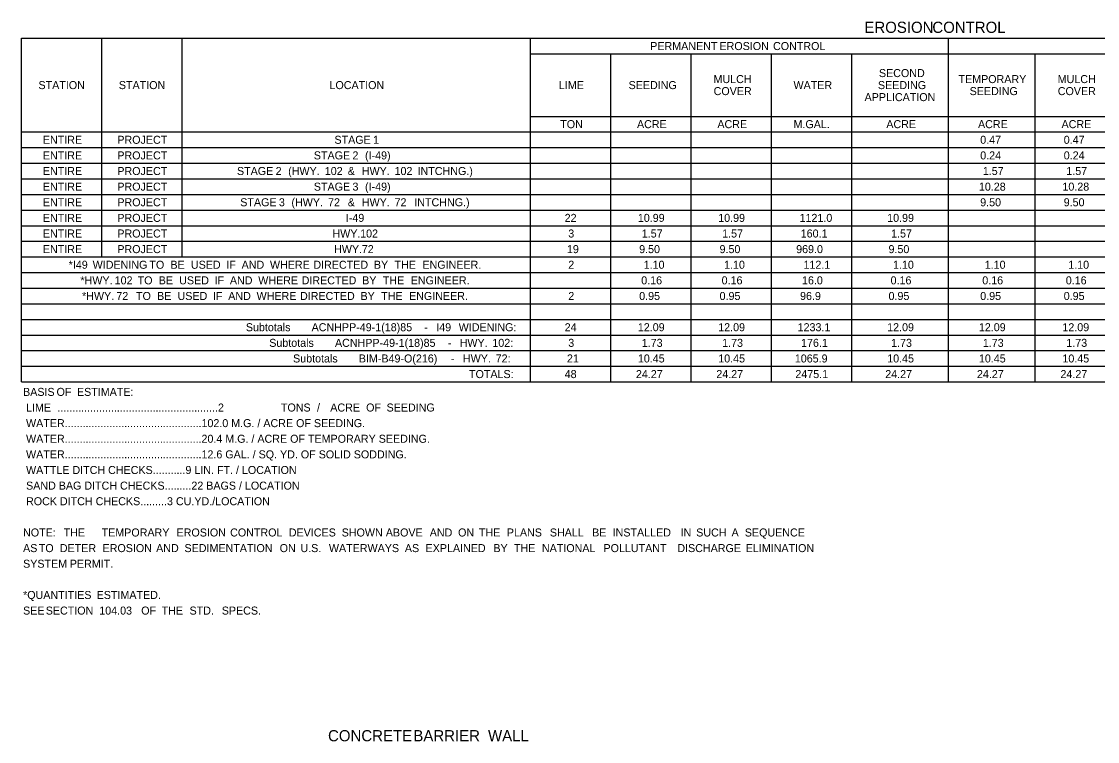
# Model space of a CAD drawing. Extents: x 1226589 to 1228130, y 151309 to 152305.
# Drawn here: x 1226589 to 1227261, y 151844 to 152293 of the extents above; entities that cross this region are included whole.
import ezdxf

# ---------------------------------------------------------------- set-up
doc = ezdxf.new("R2010")
doc.units = 0
doc.layers.add('R_Dimension', color=7, linetype='Continuous')

msp = doc.modelspace()

# ---------------------------------------------------------------- linework, layer by layer
at = {"layer": 'R_Dimension'}
for p, q in [((1226588.59, 152283.05), (1227732.75, 152283.05)), ((1226588.59, 152068.55), (1226588.59, 152283.05)), ((1226638.8, 152146.55), (1226638.8, 152283.05)), ((1226689.01, 152146.55), (1226689.01, 152283.05)), ((1226906.44, 152068.55), (1226906.44, 152283.05)), ((1227167.74, 152068.55), (1227167.74, 152283.05)), ((1226906.44, 152273.3), (1227732.75, 152273.3)), ((1226956.65, 152068.55), (1226956.65, 152273.3)), ((1227006.86, 152068.55), (1227006.86, 152273.3)), ((1227057.07, 152068.55), (1227057.07, 152273.3)), ((1227107.29, 152068.55), (1227107.29, 152273.3)), ((1227221.85, 152068.55), (1227221.85, 152273.3)), ((1226906.44, 152234.3), (1227732.75, 152234.3)), ((1226588.59, 152224.55), (1227732.75, 152224.55)), ((1226588.59, 152214.8), (1227732.75, 152214.8)), ((1226588.59, 152205.05), (1227732.75, 152205.05)), ((1226588.59, 152195.3), (1227732.75, 152195.3)), ((1226588.59, 152185.55), (1227732.75, 152185.55)), ((1226588.59, 152175.8), (1227732.75, 152175.8)), ((1226588.59, 152166.05), (1227732.75, 152166.05)), ((1226588.59, 152156.3), (1227732.75, 152156.3)), ((1226588.59, 152146.55), (1227732.75, 152146.55)), ((1226588.59, 152136.8), (1227732.75, 152136.8)), ((1226588.59, 152127.05), (1227732.75, 152127.05)), ((1226588.59, 152117.3), (1227732.75, 152117.3)), ((1226588.59, 152107.55), (1227732.75, 152107.55)), ((1226588.59, 152097.8), (1227732.75, 152097.8)), ((1226588.59, 152088.05), (1227732.75, 152088.05)), ((1226588.59, 152078.3), (1227732.75, 152078.3)), ((1226588.59, 152068.55), (1227732.75, 152068.55))]:
    msp.add_line(p, q, dxfattribs=at)

# ---------------------------------------------------------------- texts
for s, height, p in [('EROSION', 7, (1227115.09, 152286.37)), (' CONTROL', 7, (1227154.94, 152286.37)), ('PERMANENT', 5, (1226981.34, 152275.67)), (' EROSION', 5, (1227022.72, 152275.67)), (' CONTROL', 5, (1227056.18, 152275.67)), ('SECOND', 5, (1227124.19, 152258.8)), ('STATION', 5, (1226599.19, 152251.3)), ('STATION', 5, (1226649.4, 152251.3)), ('LOCATION', 5, (1226780.97, 152251.3)), ('LIME', 5, (1226924.26, 152251.3)), ('SEEDING', 5, (1226967.8, 152251.3)), ('MULCH', 5, (1227020.87, 152255.05)), ('WATER', 5, (1227070.82, 152251.3)), ('SEEDING', 5, (1227123.56, 152251.3)), ('TEMPORARY', 5, (1227173.89, 152255.05)), ('MULCH', 5, (1227235.85, 152255.05)), ('COVER', 5, (1227020.93, 152247.55)), ('APPLICATION', 5, (1227115.21, 152243.8)), ('SEEDING', 5, (1227180.84, 152247.55)), ('COVER', 5, (1227235.91, 152247.55)), ('TON', 5, (1226925.11, 152226.92)), ('ACRE', 5, (1226973.06, 152226.92)), ('ACRE', 5, (1227023.27, 152226.92)), ('M.GAL.', 5, (1227070.84, 152226.92)), ('ACRE', 5, (1227128.81, 152226.92)), ('ACRE', 5, (1227186.09, 152226.92)), ('ACRE', 5, (1227238.26, 152226.92)), ('ENTIRE', 5, (1226601.92, 152217.17)), ('PROJECT', 5, (1226648.45, 152217.17)), ('STAGE', 5, (1226784.08, 152217.17)), (' 1', 5, (1226806.37, 152217.17)), ('0.47', 5, (1227187.47, 152217.17)), ('0.47', 5, (1227239.63, 152217.17)), ('ENTIRE', 5, (1226601.92, 152207.42)), ('PROJECT', 5, (1226648.45, 152207.42)), ('STAGE', 5, (1226771.19, 152207.42)), (' 2', 5, (1226793.47, 152207.42)), (' (I-49)', 5, (1226801.31, 152207.42)), ('0.24', 5, (1227187.47, 152207.42)), ('0.24', 5, (1227239.63, 152207.42)), ('ENTIRE', 5, (1226601.92, 152197.67)), ('PROJECT', 5, (1226648.45, 152197.67)), ('STAGE', 5, (1226723.18, 152197.67)), (' 2', 5, (1226745.46, 152197.67)), (' (HWY.', 5, (1226753.3, 152197.67)), (' 102', 5, (1226776.17, 152197.67)), (' &', 5, (1226790.54, 152197.67)), (' HWY.', 5, (1226799.32, 152197.67)), (' 102', 5, (1226819.75, 152197.67)), (' INTCHNG.)', 5, (1226834.12, 152197.67)), ('1.57', 5, (1227189.08, 152197.67)), ('1.57', 5, (1227241.25, 152197.67)), ('ENTIRE', 5, (1226601.92, 152187.92)), ('PROJECT', 5, (1226648.45, 152187.92)), ('STAGE', 5, (1226771.19, 152187.92)), (' 3', 5, (1226793.47, 152187.92)), (' (I-49)', 5, (1226801.31, 152187.92)), ('10.28', 5, (1227186.64, 152187.92)), ('10.28', 5, (1227238.81, 152187.92)), ('ENTIRE', 5, (1226601.92, 152178.17)), ('PROJECT', 5, (1226648.45, 152178.17)), ('STAGE', 5, (1226725.22, 152178.17)), (' 3', 5, (1226747.51, 152178.17)), (' (HWY.', 5, (1226755.34, 152178.17)), (' 72', 5, (1226778.22, 152178.17)), (' &', 5, (1226790.54, 152178.17)), (' HWY.', 5, (1226799.32, 152178.17)), (' 72', 5, (1226819.75, 152178.17)), (' INTCHNG.)', 5, (1226832.08, 152178.17)), ('9.50', 5, (1227187.45, 152178.17)), ('9.50', 5, (1227239.61, 152178.17)), ('ENTIRE', 5, (1226601.92, 152168.42)), ('PROJECT', 5, (1226648.45, 152168.42)), ('I-49', 5, (1226791.17, 152168.42)), ('22', 5, (1226927.88, 152168.42)), ('10.99', 5, (1226973.59, 152168.42)), ('10.99', 5, (1227023.8, 152168.42)), ('1121.0', 5, (1227074.6, 152168.42)), ('10.99', 5, (1227129.34, 152168.42)), ('ENTIRE', 5, (1226601.92, 152158.67)), ('PROJECT', 5, (1226648.45, 152158.67)), ('HWY.', 5, (1226782.82, 152158.67)), (' 102', 5, (1226798.26, 152158.67)), ('3', 5, (1226930.13, 152158.67)), ('1.57', 5, (1226976.05, 152158.67)), ('1.57', 5, (1227026.26, 152158.67)), ('160.1', 5, (1227075.33, 152158.67)), ('1.57', 5, (1227131.8, 152158.67)), ('ENTIRE', 5, (1226601.92, 152148.92)), ('PROJECT', 5, (1226648.45, 152148.92)), ('HWY.', 5, (1226783.85, 152148.92)), (' 72', 5, (1226799.28, 152148.92)), ('19', 5, (1226929.28, 152148.92)), ('9.50', 5, (1226974.41, 152148.92)), ('9.50', 5, (1227024.63, 152148.92)), ('969.0', 5, (1227072.48, 152148.92)), ('9.50', 5, (1227130.17, 152148.92)), ('*I49', 5, (1226618.06, 152139.17)), (' WIDENING', 5, (1226631.17, 152139.17)), (' TO', 5, (1226666.61, 152139.17)), (' BE', 5, (1226679.76, 152139.17)), (' USED', 5, (1226692.55, 152139.17)), (' IF', 5, (1226714.68, 152139.17)), (' AND', 5, (1226724.21, 152139.17)), (' WHERE', 5, (1226741.92, 152139.17)), (' DIRECTED', 5, (1226769.05, 152139.17)), (' BY', 5, (1226806.84, 152139.17)), (' THE', 5, (1226819.72, 152139.17)), (' ENGINEER.', 5, (1226837.16, 152139.17)), ('2', 5, (1226930.13, 152139.17)), ('1.10', 5, (1226977.25, 152139.17)), ('1.10', 5, (1227027.46, 152139.17)), ('112.1', 5, (1227077.06, 152139.17)), ('1.10', 5, (1227133, 152139.17)), ('1.10', 5, (1227190.29, 152139.17)), ('1.10', 5, (1227242.45, 152139.17)), ('*HWY.', 5, (1226625.39, 152129.42)), (' 102', 5, (1226644.91, 152129.42)), (' TO', 5, (1226659.28, 152129.42)), (' BE', 5, (1226672.43, 152129.42)), (' USED', 5, (1226685.23, 152129.42)), (' IF', 5, (1226707.35, 152129.42)), (' AND', 5, (1226716.88, 152129.42)), (' WHERE', 5, (1226734.6, 152129.42)), (' DIRECTED', 5, (1226761.72, 152129.42)), (' BY', 5, (1226799.52, 152129.42)), (' THE', 5, (1226812.39, 152129.42)), (' ENGINEER.', 5, (1226829.84, 152129.42)), ('0.16', 5, (1226975.71, 152129.42)), ('0.16', 5, (1227025.93, 152129.42)), ('16.0', 5, (1227076.14, 152129.42)), ('0.16', 5, (1227131.47, 152129.42)), ('0.16', 5, (1227188.75, 152129.42)), ('0.16', 5, (1227240.91, 152129.42)), ('*HWY.', 5, (1226626.41, 152119.67)), (' 72', 5, (1226645.94, 152119.67)), (' TO', 5, (1226658.26, 152119.67)), (' BE', 5, (1226671.41, 152119.67)), (' USED', 5, (1226684.21, 152119.67)), (' IF', 5, (1226706.33, 152119.67)), (' AND', 5, (1226715.86, 152119.67)), (' WHERE', 5, (1226733.58, 152119.67)), (' DIRECTED', 5, (1226760.7, 152119.67)), (' BY', 5, (1226798.5, 152119.67)), (' THE', 5, (1226811.37, 152119.67)), (' ENGINEER.', 5, (1226828.81, 152119.67)), ('2', 5, (1226930.13, 152119.67)), ('0.95', 5, (1226974.43, 152119.67)), ('0.95', 5, (1227024.65, 152119.67)), ('96.9', 5, (1227074.92, 152119.67)), ('0.95', 5, (1227130.19, 152119.67)), ('0.95', 5, (1227187.47, 152119.67)), ('0.95', 5, (1227239.63, 152119.67)), ('Subtotals', 5, (1226728.73, 152100.17)), (' ACNHPP-49-1(18)85', 5, (1226767.94, 152100.17)), (' -', 5, (1226838.37, 152100.17)), (' I49', 5, (1226845.81, 152100.17)), (' WIDENING:', 5, (1226859.83, 152100.17)), ('24', 5, (1226927.88, 152100.17)), ('12.09', 5, (1226973.59, 152100.17)), ('12.09', 5, (1227023.8, 152100.17)), ('1233.1', 5, (1227073.4, 152100.17)), ('12.09', 5, (1227129.34, 152100.17)), ('12.09', 5, (1227186.62, 152100.17)), ('12.09', 5, (1227238.79, 152100.17)), ('Subtotals', 5, (1226743.33, 152090.42)), (' ACNHPP-49-1(18)85', 5, (1226782.54, 152090.42)), (' HWY.', 5, (1226860.42, 152090.42)), (' 102:', 5, (1226880.85, 152090.42)), ('3', 5, (1226930.13, 152090.42)), ('1.73', 5, (1226976.05, 152090.42)), ('1.73', 5, (1227026.26, 152090.42)), ('176.1', 5, (1227075.53, 152090.42)), ('1.73', 5, (1227131.8, 152090.42)), ('1.73', 5, (1227189.08, 152090.42)), ('1.73', 5, (1227241.25, 152090.42)), (' -', 5, (1226852.98, 152090.42)), ('Subtotals', 5, (1226758.21, 152080.67)), (' BIM-B49-O(216)', 5, (1226797.43, 152080.67)), (' -', 5, (1226855.02, 152080.67)), (' HWY.', 5, (1226862.47, 152080.67)), (' 72:', 5, (1226882.9, 152080.67)), ('21', 5, (1226929.3, 152080.67)), ('10.45', 5, (1226973.61, 152080.67)), ('10.45', 5, (1227023.82, 152080.67)), ('1065.9', 5, (1227071.65, 152080.67)), ('10.45', 5, (1227129.36, 152080.67)), ('10.45', 5, (1227186.64, 152080.67)), ('10.45', 5, (1227238.81, 152080.67)), ('TOTALS:', 5, (1226868.13, 152070.92)), ('48', 5, (1226927.88, 152070.92)), ('24.27', 5, (1226972.39, 152070.92)), ('24.27', 5, (1227022.6, 152070.92)), ('2475.1', 5, (1227071.98, 152070.92)), ('24.27', 5, (1227128.14, 152070.92)), ('24.27', 5, (1227185.42, 152070.92)), ('24.27', 5, (1227237.59, 152070.92)), ('BASIS', 5, (1226589.56, 152059.8)), (' OF', 5, (1226608.62, 152059.8)), (' ESTIMATE:', 5, (1226621.37, 152059.8)), (' LIME', 5, (1226589.56, 152050.05)), (' ......................................................2', 5, (1226609.13, 152050.05)), (' TONS', 5, (1226748.77, 152050.05)), (' /', 5, (1226771.33, 152050.05)), (' ACRE', 5, (1226779.6, 152050.05)), (' OF', 5, (1226802, 152050.05)), (' SEEDING', 5, (1226814.76, 152050.05)), (' WATER..............................................102.0 M.G. / ACRE OF SEEDING.', 5, (1226589.56, 152040.3)), (' WATER..............................................20.4 M.G. / ACRE OF TEMPORARY SEEDING.', 5, (1226589.56, 152030.55)), (' WATER..............................................12.6 GAL. / SQ. YD. OF SOLID SODDING.', 5, (1226589.56, 152020.8)), (' WATTLE DITCH CHECKS...........9 LIN. FT. / LOCATION', 5, (1226589.56, 152011.05)), (' SAND BAG DITCH CHECKS.........22 BAGS / LOCATION', 5, (1226589.56, 152001.3)), (' ROCK DITCH CHECKS.........3 CU.YD./LOCATION', 5, (1226589.56, 151991.55)), ('NOTE:', 5, (1226589.56, 151972.05)), ('   THE', 5, (1226609.33, 151972.05)), (' TEMPORARY', 5, (1226636.77, 151972.05)), (' EROSION', 5, (1226683.58, 151972.05)), (' CONTROL', 5, (1226717.04, 151972.05)), (' DEVICES', 5, (1226753.7, 151972.05)), (' SHOWN', 5, (1226786.73, 151972.05)), (' ABOVE', 5, (1226814.29, 151972.05)), (' AND', 5, (1226841.73, 151972.05)), (' ON', 5, (1226859.44, 151972.05)), (' THE', 5, (1226872.44, 151972.05)), (' PLANS', 5, (1226889.88, 151972.05)), (' SHALL', 5, (1226916.77, 151972.05)), (' BE', 5, (1226943.18, 151972.05)), (' INSTALLED', 5, (1226955.98, 151972.05)), (' IN', 5, (1226998.42, 151972.05)), (' SUCH', 5, (1227008.18, 151972.05)), (' A', 5, (1227030.27, 151972.05)), (' SEQUENCE', 5, (1227038.54, 151972.05)), ('AS', 5, (1226589.56, 151962.3)), (' TO', 5, (1226597.52, 151962.3)), (' DETER', 5, (1226610.66, 151962.3)), (' EROSION', 5, (1226637.36, 151962.3)), (' AND', 5, (1226670.82, 151962.3)), (' SEDIMENTATION', 5, (1226688.54, 151962.3)), (' ON', 5, (1226747.99, 151962.3)), (' U.S.', 5, (1226760.98, 151962.3)), (' WATERWAYS', 5, (1226778.74, 151962.3)), (' AS', 5, (1226826.18, 151962.3)), (' EXPLAINED', 5, (1226839.13, 151962.3)), (' BY', 5, (1226881.49, 151962.3)), (' THE', 5, (1226894.37, 151962.3)), (' NATIONAL', 5, (1226911.81, 151962.3)), (' POLLUTANT', 5, (1226950.27, 151962.3)), (' DISCHARGE', 5, (1226996.41, 151962.3)), (' ELIMINATION', 5, (1227039.13, 151962.3)), ('SYSTEM', 5, (1226589.56, 151952.55)), (' PERMIT.', 5, (1226616.89, 151952.55)), ('*QUANTITIES', 5, (1226589.56, 151933.05)), (' ESTIMATED.', 5, (1226633.66, 151933.05)), ('SEE', 5, (1226589.56, 151923.3)), (' SECTION', 5, (1226601.85, 151923.3)), (' 104.03', 5, (1226635.31, 151923.3)), (' OF', 5, (1226661.49, 151923.3)), (' THE', 5, (1226674.25, 151923.3)), (' STD.', 5, (1226691.69, 151923.3)), (' SPECS.', 5, (1226711.81, 151923.3)), ('CONCRETE', 7, (1226780.06, 151844.2)), (' BARRIER', 7, (1226830.77, 151844.2)), (' WALL', 7, (1226877.4, 151844.2))]:
    msp.add_text(s, height=height, dxfattribs=at).set_placement(p)

doc.saveas('drawing.dxf')
